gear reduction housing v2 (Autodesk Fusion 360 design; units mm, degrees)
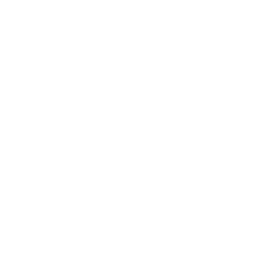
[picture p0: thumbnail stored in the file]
parameter "Drive_Gear_Dia" = 96 (= "( ( Drive_Gear_Teeth * Gear_Module ) * 1 mm )")
parameter "Driven_Gear_Dia" = 32 (= "( ( Driven_Gear_Teeth * Gear_Module ) * 1 mm )")
parameter "Idle_Gear_Dia" = 20 (= "( ( Idle_Gear_Teeth * Gear_Module ) * 1 mm )")
parameter "Mount_Bolts" = 8
parameter "Idle_Gear_Shaft" = 8
parameter "Mount_Bolt_Flange" = 12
